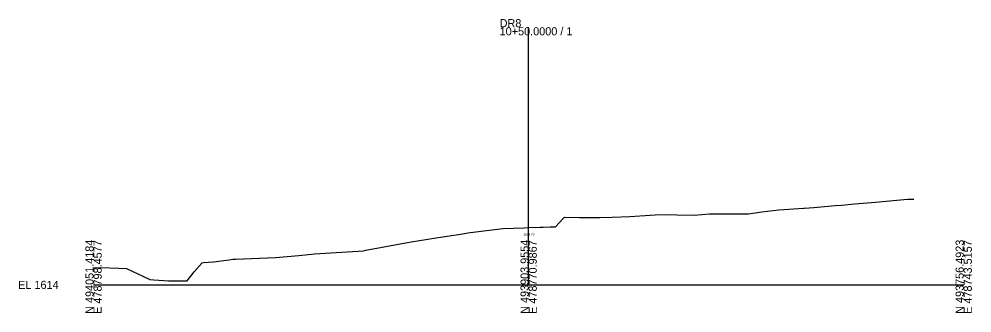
# Model space of a CAD drawing. Extents: x 24 to 353, y -10 to 3552.
# Drawn here: x 24.3 to 352.8, y 490.3 to 591.8 of the extents above; entities that cross this region are included whole.
import ezdxf

# ---------------------------------------------------------------- set-up
doc = ezdxf.new("R2010")
doc.units = 0
for name, color, linetype in [('Exist Cross Section Cell', 7, 'Continuous'), ('Exist XS Center Line Elevation Label', 7, 'Continuous'), ('Exist XS Ground Line', 7, 'Continuous'), ('Scratch_Level_5', 7, 'Continuous')]:
    doc.layers.add(name, color=color, linetype=linetype)

msp = doc.modelspace()

# ---------------------------------------------------------------- linework, layer by layer
at = {"layer": 'Exist Cross Section Cell'}
for p, q in [((200, 500), (200, 588.95)), ((50, 500), (200, 500)), ((200, 500), (350, 500))]:
    msp.add_line(p, q, dxfattribs=at)
at = {"layer": 'Exist XS Ground Line'}
msp.add_lwpolyline([(50, 505.86), (52.44, 505.97), (58.76, 505.78), (61.39, 505.65), (67.16, 502.93), (69.44, 501.87), (70.75, 501.75), (75.81, 501.43), (80.75, 501.45), (82.26, 501.44), (84.68, 504.46), (87.4, 507.66), (87.86, 507.7), (91.34, 507.94), (96.7, 508.68), (98.01, 508.88), (98.91, 508.91), (112.77, 509.47), (120.75, 510.18), (126.15, 510.68), (143.05, 511.81), (143.82, 511.95), (159.47, 514.91), (168.07, 516.22), (169.64, 516.43), (176.53, 517.57), (179.82, 518.1), (180.82, 518.23), (191.1, 519.42), (194.73, 519.57), (198.56, 519.75), (200, 519.79), (204.02, 519.89), (204.99, 519.9), (207.4, 520.02), (209.22, 520.08), (211.96, 522.94), (212.35, 523.35), (217.55, 523.3), (224.55, 523.26), (228.78, 523.36), (234.9, 523.64), (243.63, 524.23), (247.56, 524.32), (251.14, 524.22), (257.03, 524.07), (262.34, 524.51), (275.75, 524.58), (280.42, 525.18), (286.25, 525.92), (294.8, 526.46), (295.16, 526.49), (298.34, 526.72), (305.7, 527.36), (307.9, 527.51), (312.44, 527.95), (319.61, 528.58), (330.61, 529.57), (332.43, 529.65), (332.78, 529.64)], dxfattribs=at)
at = {"layer": 'Scratch_Level_5'}
msp.add_lwpolyline([(50, 505.86), (52.44, 505.97), (58.76, 505.78), (61.39, 505.65), (67.16, 502.93), (69.44, 501.87), (70.75, 501.75), (75.81, 501.43), (80.75, 501.45), (82.26, 501.44), (84.68, 504.46), (87.4, 507.66), (87.86, 507.7), (91.34, 507.94), (96.7, 508.68), (98.01, 508.88), (98.91, 508.91), (112.77, 509.47), (120.75, 510.18), (126.15, 510.68), (143.05, 511.81), (143.82, 511.95), (159.47, 514.91), (168.07, 516.22), (169.64, 516.43), (176.53, 517.57), (179.82, 518.1), (180.82, 518.23), (191.1, 519.42), (194.73, 519.57), (198.56, 519.75), (200, 519.79), (204.02, 519.89), (204.99, 519.9), (207.4, 520.02), (209.22, 520.08), (211.96, 522.94), (212.35, 523.35), (217.55, 523.3), (224.55, 523.26), (228.78, 523.36), (234.9, 523.64), (243.63, 524.23), (247.56, 524.32), (251.14, 524.22), (257.03, 524.07), (262.34, 524.51), (275.75, 524.58), (280.42, 525.18), (286.25, 525.92), (294.8, 526.46), (295.16, 526.49), (298.34, 526.72), (305.7, 527.36), (307.9, 527.51), (312.44, 527.95), (319.61, 528.58), (330.61, 529.57), (332.43, 529.65), (332.78, 529.64)], dxfattribs=at)

# ---------------------------------------------------------------- texts
at = {"layer": 'Exist Cross Section Cell'}
for s, p in [('DR8', (190, 588.95)), ('10+50.0000 / 1', (190, 586.15)), ('EL 1614', (24, 498.6))]:
    msp.add_text(s, height=2.8, dxfattribs=at).set_placement(p)
for s, p in [('N 494051.4184', (50, 490)), ('E 478798.4577', (52.8, 490)), ('N 493903.9554', (200, 490)), ('E 478770.9867', (202.8, 490)), ('N 493756.4923', (350, 490)), ('E 478743.5157', (352.8, 490))]:
    msp.add_text(s, height=2.8, rotation=90, dxfattribs=at).set_placement(p)
at = {"layer": 'Exist XS Center Line Elevation Label'}
msp.add_text('1633.79', height=0.75, dxfattribs=at).set_placement((198.23, 517.04))

doc.saveas('drawing.dxf')
